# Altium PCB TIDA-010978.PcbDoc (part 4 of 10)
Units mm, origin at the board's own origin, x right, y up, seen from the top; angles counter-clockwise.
Board outline 243.95 x 94.85 mm, 4 copper layers (Top Layer, Mid Layer 1, Mid Layer 2, Bottom Layer), stack 1.623 mm thick; 865 components, 374 nets, 2308 pads, 2132 vias.
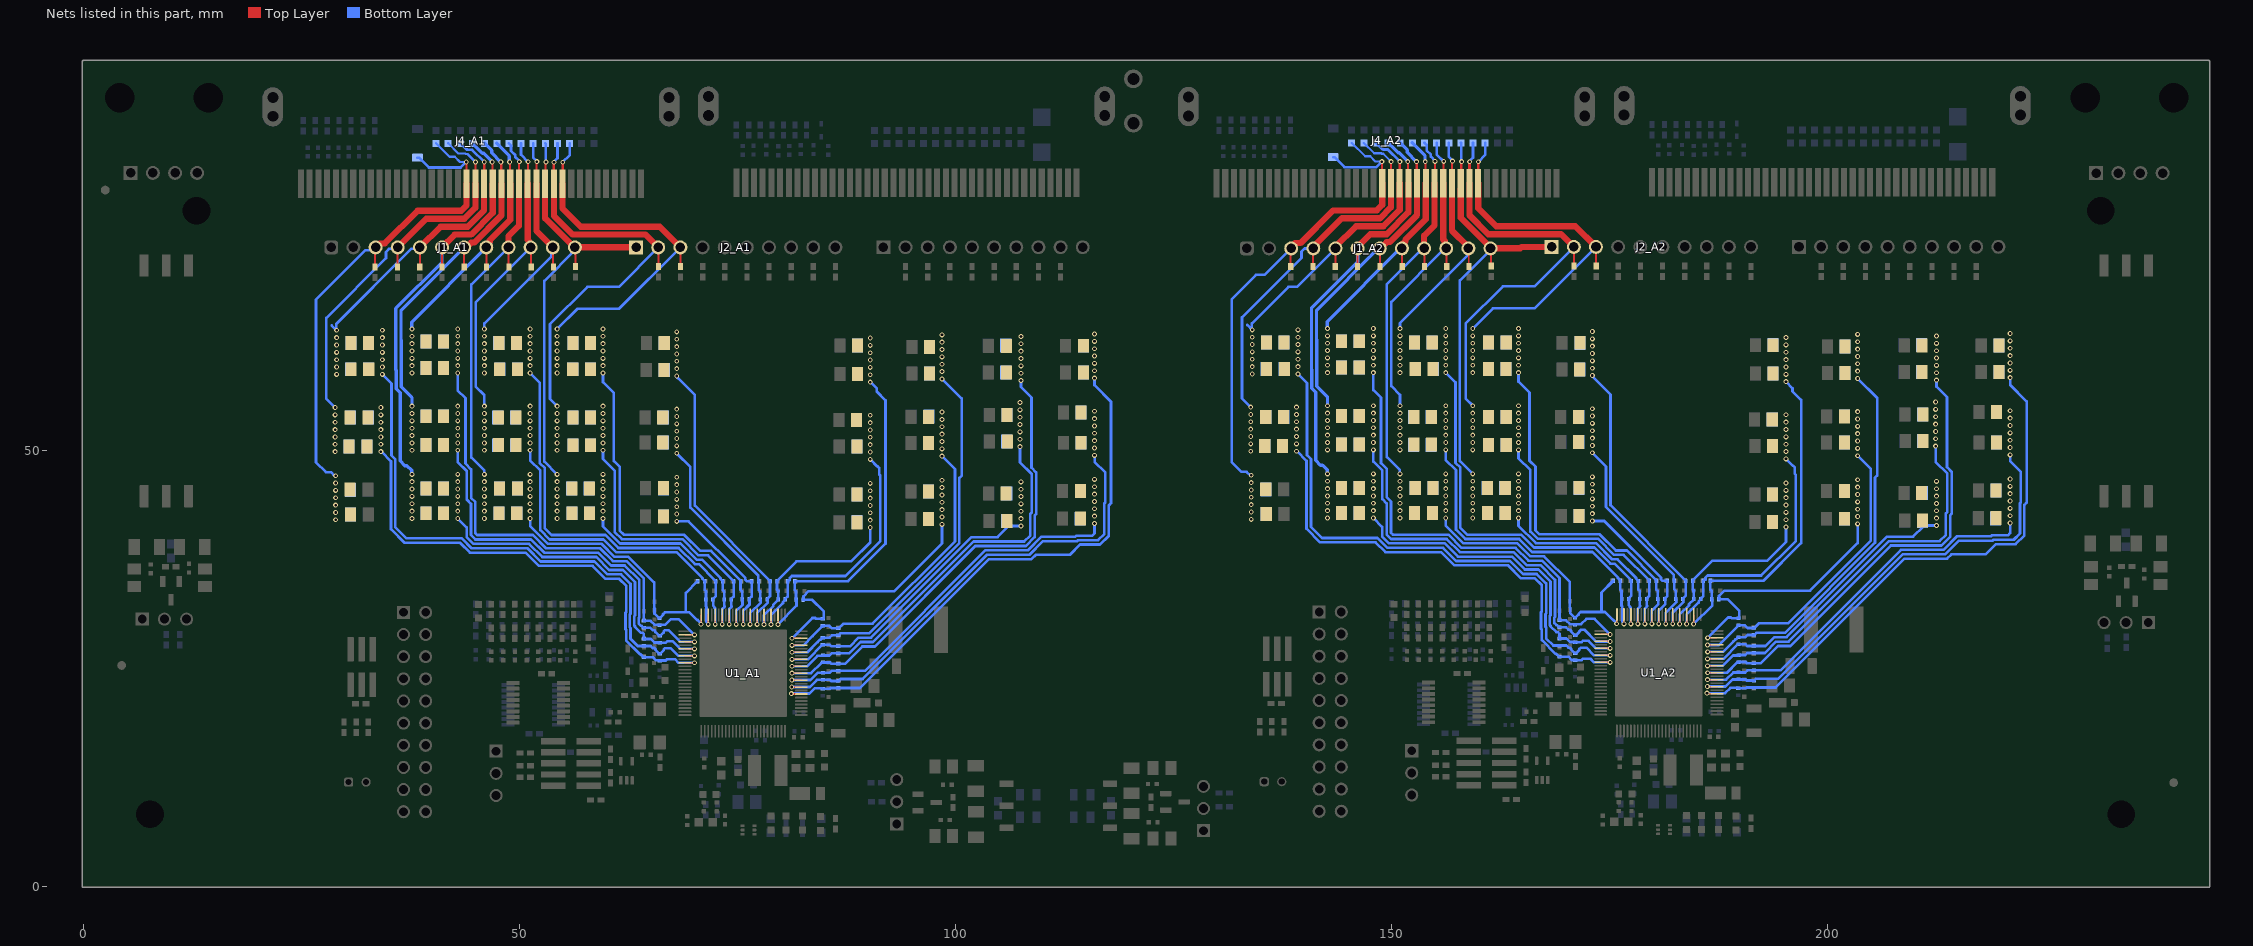
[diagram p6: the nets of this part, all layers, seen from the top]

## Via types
v1: diameter 0.559, hole 0.305, Top Layer to Bottom Layer, tented both sides, 1735 vias
v2: diameter 0.47, hole 0.2, Top Layer to Bottom Layer, tented both sides, 269 vias
v3: diameter 0.5, hole 0.2, Top Layer to Bottom Layer, tented both sides, 128 vias

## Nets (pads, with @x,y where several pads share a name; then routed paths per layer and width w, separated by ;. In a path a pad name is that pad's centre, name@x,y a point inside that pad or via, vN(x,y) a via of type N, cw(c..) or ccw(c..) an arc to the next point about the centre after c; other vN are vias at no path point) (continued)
CB1_A1: C46_A1.1 C53_A1.2 R100_A1.2 R107_A1.2 R112_A1.2 R117_A1.2 U1_A1.60 | length 55.6
  Top Layer w0.178: U1_A1.60@68.982,25.649 68.987,25.644 70.066,25.644 v1(70.071,25.639)
  Bottom Layer w0.305: v1(34.11,49.854) 34.158,49.854 35.265,48.748 35.265,40.965 36.825,39.405 43.183,39.405 44.317,38.271 50.7,38.271 52.214,36.757 58.392,36.757 59.874,35.274 61.443,35.274 62.235,34.482 62.235,31.473 62.155,31.393 62.155,29.506 62.235,29.426 62.235,28.18 63.797,26.618 63.897,26.618 64.222,26.293 65.285,26.293 65.66,25.918 66.037,25.918 C46_A1.1@66.085,25.871 66.114,25.9 66.792,25.9 66.944,26.053 67.815,26.053 68.229,25.639 v1(70.071,25.639)
  other v1: 34.11,50.697 34.11,51.54 34.11,52.383 34.11,53.226 34.11,54.069 34.11,54.912
CB1_A2: C46_A2.1 C53_A2.2 R100_A2.2 R107_A2.2 R112_A2.2 R117_A2.2 U1_A2.60 | length 55.6
  Top Layer w0.178: U1_A2.60@173.982,25.699 173.987,25.694 175.066,25.694 v1(175.071,25.689)
  Bottom Layer w0.305: v1(139.11,49.904) 139.158,49.904 140.265,48.798 140.265,41.015 141.825,39.455 148.183,39.455 149.317,38.321 155.7,38.321 157.214,36.807 163.392,36.807 164.874,35.324 166.443,35.324 167.235,34.532 167.235,31.523 167.155,31.443 167.155,29.556 167.235,29.476 167.235,28.23 168.797,26.668 168.897,26.668 169.222,26.343 170.285,26.343 170.66,25.968 171.037,25.968 C46_A2.1@171.085,25.921 171.114,25.95 171.792,25.95 171.944,26.103 172.815,26.103 173.229,25.689 v1(175.071,25.689)
  other v1: 139.11,50.747 139.11,51.59 139.11,52.433 139.11,53.276 139.11,54.119 139.11,54.962
CB2_A1: C42_A1.1 C46_A1.2 R80_A1.2 R85_A1.2 R90_A1.2 R95_A1.2 U1_A1.58 | length 64
  Top Layer w0.178: U1_A1.58@68.982,26.449 68.987,26.444 70.066,26.444 v1(70.071,26.439)
  Bottom Layer w0.305: v1(34.28,58.713) 35.318,57.674 35.318,49.408 35.769,48.957 35.769,41.174 37.034,39.909 43.392,39.909 44.526,38.776 50.909,38.776 52.423,37.262 58.601,37.262 60.083,35.779 61.652,35.779 62.74,34.691 62.74,31.264 62.66,31.184 62.66,29.715 62.74,29.635 62.74,28.397 63.565,27.572 C42_A1.1@64.272,27.572 65.044,27.572 65.282,27.333 65.464,27.333 65.593,27.205 65.593,27.112 66.035,26.671 C46_A1.2@66.085,26.671 ; C46_A1.2@66.135,26.671 66.533,27.069 66.533,27.148 66.711,27.327 67.341,27.327 68.229,26.439 v1(70.071,26.439)
  other v1: 34.28,59.556 34.28,60.398 34.28,61.241 34.28,62.084 34.28,62.927 34.28,63.77
CB2_A2: C42_A2.1 C46_A2.2 R80_A2.2 R85_A2.2 R90_A2.2 R95_A2.2 U1_A2.58 | length 64
  Top Layer w0.178: U1_A2.58@173.982,26.499 173.987,26.494 175.066,26.494 v1(175.071,26.489)
  Bottom Layer w0.305: v1(139.28,58.763) 140.318,57.724 140.318,49.458 140.769,49.007 140.769,41.224 142.034,39.959 148.392,39.959 149.526,38.826 155.909,38.826 157.423,37.312 163.601,37.312 165.083,35.829 166.652,35.829 167.74,34.741 167.74,31.314 167.66,31.234 167.66,29.765 167.74,29.685 167.74,28.447 168.565,27.622 C42_A2.1@169.272,27.622 170.044,27.622 170.282,27.383 170.464,27.383 170.593,27.255 170.593,27.162 171.035,26.721 C46_A2.2@171.085,26.721 ; C46_A2.2@171.135,26.721 171.533,27.119 171.533,27.198 171.711,27.377 172.341,27.377 173.229,26.489 v1(175.071,26.489)
  other v1: 139.28,59.606 139.28,60.448 139.28,61.291 139.28,62.134 139.28,62.977 139.28,63.82
CB3_A1: C34_A1.1 C42_A1.2 R58_A1.2 R62_A1.2 R66_A1.2 R72_A1.2 U1_A1.56 | length 38.6
  Top Layer w0.178: U1_A1.56@68.982,27.249 68.987,27.244 70.066,27.244 v1(70.071,27.239)
  Bottom Layer w0.305: v1(42.921,42.194) 43.937,41.179 43.937,40.414 43.937,40.079 44.735,39.281 51.118,39.281 52.633,37.766 58.81,37.766 60.292,36.284 61.861,36.284 63.245,34.9 63.245,31.055 63.165,30.975 63.165,29.924 63.245,29.844 63.245,29.758 63.906,29.097 64.094,29.097 64.272,28.919 C42_A1.2@64.272,28.372 65.069,28.372 65.469,27.972 65.987,27.972 66.035,27.924 C34_A1.1@66.085,27.924 66.114,27.954 66.792,27.954 66.944,28.106 67.589,28.106 68.456,27.239 v1(70.071,27.239)
  other v1: 42.921,43.037 42.921,43.88 42.921,44.723 42.921,45.566 42.921,46.409 42.921,47.25
CB3_A2: C34_A2.1 C42_A2.2 R58_A2.2 R62_A2.2 R66_A2.2 R72_A2.2 U1_A2.56 | length 38.6
  Top Layer w0.178: U1_A2.56@173.982,27.299 173.987,27.294 175.066,27.294 v1(175.071,27.289)
  Bottom Layer w0.305: v1(147.921,42.244) 148.937,41.229 148.937,40.464 148.937,40.129 149.735,39.331 156.118,39.331 157.633,37.816 163.81,37.816 165.292,36.334 166.861,36.334 168.245,34.95 168.245,31.105 168.165,31.025 168.165,29.974 168.245,29.894 168.245,29.808 168.906,29.147 169.094,29.147 169.272,28.969 C42_A2.2@169.272,28.422 170.069,28.422 170.469,28.022 170.987,28.022 171.035,27.974 C34_A2.1@171.085,27.974 171.114,28.004 171.792,28.004 171.944,28.156 172.589,28.156 173.456,27.289 v1(175.071,27.289)
  other v1: 147.921,43.087 147.921,43.93 147.921,44.773 147.921,45.616 147.921,46.459 147.921,47.3
CB4_A1: C25_A1.1 C34_A1.2 R38_A1.2 R42_A1.2 R46_A1.2 R51_A1.2 U1_A1.54 | length 45.8
  Top Layer w0.178: U1_A1.54@68.982,28.049 68.987,28.044 70.066,28.044 v1(70.071,28.039)
  Bottom Layer w0.305: v1(42.921,50.01) 42.921,48.655 43.957,47.619 43.957,44.35 44.442,43.865 44.442,40.919 44.442,40.288 44.944,39.786 51.327,39.786 52.842,38.271 59.019,38.271 60.502,36.789 62.07,36.789 63.75,35.109 63.75,30.846 63.67,30.766 63.67,30.133 63.906,29.897 63.975,29.897 64.175,29.697 64.225,29.697 C25_A1.1@64.272,29.65 65.008,29.65 65.276,29.381 65.459,29.381 65.588,29.252 65.588,29.171 66.035,28.724 66.135,28.724 66.533,29.122 66.533,29.202 66.711,29.38 67.114,29.38 68.456,28.039 v1(70.071,28.039)
  other v1: 42.921,50.853 42.921,51.696 42.921,52.539 42.921,53.382 42.921,54.225 42.921,55.068
CB4_A2: C25_A2.1 C34_A2.2 R38_A2.2 R42_A2.2 R46_A2.2 R51_A2.2 U1_A2.54 | length 45.8
  Top Layer w0.178: U1_A2.54@173.982,28.099 173.987,28.094 175.066,28.094 v1(175.071,28.089)
  Bottom Layer w0.305: v1(147.921,50.06) 147.921,48.705 148.957,47.669 148.957,44.4 149.442,43.915 149.442,40.969 149.442,40.338 149.944,39.836 156.327,39.836 157.842,38.321 164.019,38.321 165.502,36.839 167.07,36.839 168.75,35.159 168.75,30.896 168.67,30.816 168.67,30.183 168.906,29.947 168.975,29.947 169.175,29.747 169.225,29.747 C25_A2.1@169.272,29.7 170.008,29.7 170.276,29.431 170.459,29.431 170.588,29.302 170.588,29.221 171.035,28.774 171.135,28.774 171.533,29.172 171.533,29.252 171.711,29.43 172.114,29.43 173.456,28.089 v1(175.071,28.089)
  other v1: 147.921,50.903 147.921,51.746 147.921,52.589 147.921,53.432 147.921,54.275 147.921,55.118
CB5_A1: C12_A1.1 C25_A1.2 R21_A1.2 R25_A1.2 R29_A1.2 R33_A1.2 U1_A1.52 | length 53.6
  Top Layer w0.178: U1_A1.52@68.982,28.849 68.987,28.844 70.066,28.844 v1(70.071,28.839)
  Bottom Layer w0.305: v1(42.921,58.869) 42.921,56.873 43.804,55.989 43.804,48.486 44.462,47.829 44.462,44.559 44.947,44.074 44.947,41.337 44.947,40.497 45.153,40.29 51.536,40.29 53.051,38.776 59.228,38.776 60.711,37.293 62.279,37.293 64.272,35.3 C25_A1.2@64.272,30.45 65.036,30.45 65.472,30.013 65.956,30.013 66.004,29.965 C12_A1.1@66.054,29.965 66.102,30.013 66.736,30.013 67.345,30.622 68.281,30.622 70.064,28.839 v1(70.071,28.839)
  other v1: 42.921,59.712 42.921,60.555 42.921,61.398 42.921,62.24 42.921,63.083 42.921,63.926
CB5_A2: C12_A2.1 C25_A2.2 R21_A2.2 R25_A2.2 R29_A2.2 R33_A2.2 U1_A2.52 | length 53.6
  Top Layer w0.178: U1_A2.52@173.982,28.899 173.987,28.894 175.066,28.894 v1(175.071,28.889)
  Bottom Layer w0.305: v1(147.921,58.919) 147.921,56.923 148.804,56.039 148.804,48.536 149.462,47.879 149.462,44.609 149.947,44.124 149.947,41.387 149.947,40.547 150.153,40.34 156.536,40.34 158.051,38.826 164.228,38.826 165.711,37.343 167.279,37.343 169.272,35.35 C25_A2.2@169.272,30.5 170.036,30.5 170.472,30.063 170.956,30.063 171.004,30.015 C12_A2.1@171.054,30.015 171.102,30.063 171.736,30.063 172.345,30.672 173.281,30.672 175.064,28.889 v1(175.071,28.889)
  other v1: 147.921,59.762 147.921,60.605 147.921,61.448 147.921,62.29 147.921,63.133 147.921,63.976
CB6_A1: C12_A1.2 C54_A1.1 R2_A1.2 R8_A1.2 R12_A1.2 R16_A1.2 U1_A1.50 | length 33
  Top Layer w0.178: v1(70.821,30.064) 70.846,30.089 70.846,31.112 U1_A1.50@70.857,31.124
  Bottom Layer w0.305: v1(51.22,42.194) 51.22,41.32 53.26,39.281 59.437,39.281 60.92,37.798 62.488,37.798 65.447,34.84 65.447,31.955 65.488,31.913 65.488,31.281 66.004,30.765 66.104,30.765 66.465,31.127 66.465,31.206 66.681,31.422 69.083,31.422 ; 70.399,30.508 69.485,31.422 69.083,31.422 ; 70.433,30.542 70.433,30.52 70.821,30.133 v1(70.821,30.064) ; C54_A1.1@70.433,34.999 69.083,33.649 69.083,31.422
  other v1: 51.22,43.037 51.22,43.88 51.22,44.723 51.22,45.566 51.22,46.409 51.22,47.25
CB6_A2: C12_A2.2 C54_A2.1 R2_A2.2 R8_A2.2 R12_A2.2 R16_A2.2 U1_A2.50 | length 33
  Top Layer w0.178: v1(175.821,30.114) 175.846,30.139 175.846,31.162 U1_A2.50@175.857,31.174
  Bottom Layer w0.305: v1(156.22,42.244) 156.22,41.37 158.26,39.331 164.437,39.331 165.92,37.848 167.488,37.848 170.447,34.89 170.447,32.005 170.488,31.963 170.488,31.331 171.004,30.815 171.104,30.815 171.465,31.177 171.465,31.256 171.681,31.472 174.083,31.472 ; 175.399,30.558 174.485,31.472 174.083,31.472 ; 175.433,30.592 175.433,30.57 175.821,30.183 v1(175.821,30.114) ; C54_A2.1@175.433,35.049 174.083,33.699 174.083,31.472
  other v1: 156.22,43.087 156.22,43.93 156.22,44.773 156.22,45.616 156.22,46.459 156.22,47.3
CB7_A1: C47_A1.1 C54_A1.2 R101_A1.2 R108_A1.2 R113_A1.2 R118_A1.2 U1_A1.48 | length 37.2
  Top Layer w0.178: v1(71.657,30.05) U1_A1.48@71.657,31.124
  Bottom Layer w0.305: v1(51.22,50.01) 51.22,48.856 52.401,47.676 52.401,40.854 53.469,39.786 59.646,39.786 61.129,38.303 68.048,38.303 70.986,35.365 70.986,35.296 71.186,35.096 71.186,35.046 C54_A1.2@71.233,34.999 71.233,34.004 71.385,33.852 71.385,32.117 71.457,32.046 71.457,30.319 71.657,30.118 v1(71.657,30.05)
  other v1: 51.22,50.853 51.22,51.696 51.22,52.539 51.22,53.382 51.22,54.225 51.22,55.068
CB7_A2: C47_A2.1 C54_A2.2 R101_A2.2 R108_A2.2 R113_A2.2 R118_A2.2 U1_A2.48 | length 37.2
  Top Layer w0.178: v1(176.657,30.1) U1_A2.48@176.657,31.174
  Bottom Layer w0.305: v1(156.22,50.06) 156.22,48.906 157.401,47.726 157.401,40.904 158.469,39.836 164.646,39.836 166.129,38.353 173.048,38.353 175.986,35.415 175.986,35.346 176.186,35.146 176.186,35.096 C54_A2.2@176.233,35.049 176.233,34.054 176.385,33.902 176.385,32.167 176.457,32.096 176.457,30.369 176.657,30.168 v1(176.657,30.1)
  other v1: 156.22,50.903 156.22,51.746 156.22,52.589 156.22,53.432 156.22,54.275 156.22,55.118
CB8_A1: C43_A1.1 C47_A1.2 R81_A1.2 R86_A1.2 R91_A1.2 R96_A1.2 U1_A1.46 | length 46.9
  Top Layer w0.178: v1(72.457,30.05) U1_A1.46@72.457,31.124
  Bottom Layer w0.305: v1(51.22,58.869) 52.343,57.746 52.343,48.521 52.905,47.959 52.905,41.063 53.678,40.29 59.855,40.29 61.338,38.808 68.257,38.808 70.109,36.956 70.562,36.956 72.446,35.072 72.446,35.022 C43_A1.1@72.494,34.974 72.494,33.264 72.233,33.003 72.233,32.953 C47_A1.2@72.185,32.905 72.204,32.886 72.204,32.198 72.357,32.046 72.357,31.976 72.457,31.876 v1(72.457,30.05)
  other v1: 51.22,59.712 51.22,60.555 51.22,61.398 51.22,62.24 51.22,63.083 51.22,63.926
CB8_A2: C43_A2.1 C47_A2.2 R81_A2.2 R86_A2.2 R91_A2.2 R96_A2.2 U1_A2.46 | length 46.9
  Top Layer w0.178: v1(177.457,30.1) U1_A2.46@177.457,31.174
  Bottom Layer w0.305: v1(156.22,58.919) 157.343,57.796 157.343,48.571 157.905,48.009 157.905,41.113 158.678,40.34 164.855,40.34 166.338,38.858 173.257,38.858 175.109,37.006 175.562,37.006 177.446,35.122 177.446,35.072 C43_A2.1@177.494,35.024 177.494,33.314 177.233,33.053 177.233,33.003 C47_A2.2@177.185,32.955 177.204,32.936 177.204,32.248 177.357,32.096 177.357,32.026 177.457,31.926 v1(177.457,30.1)
  other v1: 156.22,59.762 156.22,60.605 156.22,61.448 156.22,62.29 156.22,63.133 156.22,63.976
CB9_A1: C35_A1.1 C43_A1.2 R59_A1.2 R63_A1.2 R67_A1.2 R73_A1.2 U1_A1.44 | length 23.5
  Top Layer w0.178: v1(73.257,30.05) U1_A1.44@73.257,31.092
  Bottom Layer w0.305: v1(59.576,42.194) 59.576,41.284 61.547,39.313 68.466,39.313 70.318,37.461 70.927,37.461 73.046,35.341 73.046,35.272 73.294,35.024 73.294,34.004 73.476,33.823 73.476,32.167 73.547,32.096 73.257,31.805 v1(73.257,30.05)
  other v1: 59.576,43.037 59.576,43.88 59.576,44.723 59.576,45.566 59.576,46.409 59.576,47.25
CB9_A2: C35_A2.1 C43_A2.2 R59_A2.2 R63_A2.2 R67_A2.2 R73_A2.2 U1_A2.44 | length 23.5
  Top Layer w0.178: v1(178.257,30.1) U1_A2.44@178.257,31.142
  Bottom Layer w0.305: v1(164.576,42.244) 164.576,41.334 166.547,39.363 173.466,39.363 175.318,37.511 175.927,37.511 178.046,35.391 178.046,35.322 178.294,35.074 178.294,34.054 178.476,33.873 178.476,32.217 178.547,32.146 178.257,31.855 v1(178.257,30.1)
  other v1: 164.576,43.087 164.576,43.93 164.576,44.773 164.576,45.616 164.576,46.459 164.576,47.3
CB10_A1: C26_A1.1 C35_A1.2 R39_A1.2 R43_A1.2 R47_A1.2 R52_A1.2 U1_A1.42 | length 32.2
  Top Layer w0.178: v1@74.065,30.028 U1_A1.42@74.065,31.1
  Bottom Layer w0.305: v1(59.576,50.01) 59.576,49.025 60.926,47.676 60.926,40.648 61.756,39.817 68.675,39.817 70.527,37.966 71.619,37.966 74.509,35.076 74.509,35.026 C26_A1.1@74.556,34.979 74.556,33.231 74.276,32.95 74.276,32.167 74.347,32.096 74.057,31.805 v1(74.057,30.05)
  other v1: 59.576,50.853 59.576,51.696 59.576,52.539 59.576,53.382 59.576,54.225 59.576,55.068
CB10_A2: C26_A2.1 C35_A2.2 R39_A2.2 R43_A2.2 R47_A2.2 R52_A2.2 U1_A2.42 | length 32.2
  Top Layer w0.178: v1@179.065,30.078 U1_A2.42@179.065,31.15
  Bottom Layer w0.305: v1(164.576,50.06) 164.576,49.075 165.926,47.726 165.926,40.698 166.756,39.867 173.675,39.867 175.527,38.016 176.619,38.016 179.509,35.126 179.509,35.076 C26_A2.1@179.556,35.029 179.556,33.281 179.276,33 179.276,32.217 179.347,32.146 179.057,31.855 v1(179.057,30.1)
  other v1: 164.576,50.903 164.576,51.746 164.576,52.589 164.576,53.432 164.576,54.275 164.576,55.118
CB11_A1: C13_A1.1 C26_A1.2 R22_A1.2 R26_A1.2 R30_A1.2 R34_A1.2 U1_A1.40 | length 41.6
  Top Layer w0.178: v1@74.865,30.028 U1_A1.40@74.865,31.1
  Bottom Layer w0.305: v1(59.576,58.869) 59.576,57.825 60.829,56.572 60.829,48.76 61.516,48.073 61.516,40.771 61.965,40.322 68.884,40.322 70.736,38.471 71.983,38.471 75.356,35.098 75.356,34.01 75.538,33.828 C13_A1.1@75.538,32.907 75.586,32.86 75.586,32.354 75.61,32.33 74.857,31.578 v1(74.857,30.05)
  other v1: 59.576,59.712 59.576,60.555 59.576,61.398 59.576,62.24 59.576,63.083 59.576,63.926
CB11_A2: C13_A2.1 C26_A2.2 R22_A2.2 R26_A2.2 R30_A2.2 R34_A2.2 U1_A2.40 | length 41.6
  Top Layer w0.178: v1@179.865,30.078 U1_A2.40@179.865,31.15
  Bottom Layer w0.305: v1(164.576,58.919) 164.576,57.875 165.829,56.622 165.829,48.81 166.516,48.123 166.516,40.821 166.965,40.372 173.884,40.372 175.736,38.521 176.983,38.521 180.356,35.148 180.356,34.06 180.538,33.878 C13_A2.1@180.538,32.957 180.586,32.91 180.586,32.404 180.61,32.38 179.857,31.628 v1(179.857,30.1)
  other v1: 164.576,59.762 164.576,60.605 164.576,61.448 164.576,62.29 164.576,63.133 164.576,63.976
CB12_A1: C13_A1.2 C55_A1.1 R3_A1.2 R9_A1.2 R13_A1.2 R17_A1.2 U1_A1.38 | length 18
  Top Layer w0.178: v1(75.657,30.05) U1_A1.38@75.657,31.092
  Bottom Layer w0.305: v1(68.032,41.854) 69.4,41.854 75.909,35.345 75.909,35.163 76.087,34.984 C55_A1.1@76.631,34.984 76.631,33.25 76.338,32.957 C13_A1.2@76.338,32.907 76.386,32.86 76.386,32.378 76.41,32.354 75.657,31.602 v1(75.657,30.05)
  other v1: 68.032,42.697 68.032,43.54 68.032,44.383 68.032,45.225 68.032,46.068 68.032,46.911
CB12_A2: C13_A2.2 C55_A2.1 R3_A2.2 R9_A2.2 R13_A2.2 R17_A2.2 U1_A2.38 | length 18
  Top Layer w0.178: v1(180.657,30.1) U1_A2.38@180.657,31.142
  Bottom Layer w0.305: v1(173.032,41.904) 174.4,41.904 180.909,35.395 180.909,35.213 181.087,35.034 C55_A2.1@181.631,35.034 181.631,33.3 181.338,33.007 C13_A2.2@181.338,32.957 181.386,32.91 181.386,32.428 181.41,32.404 180.657,31.652 v1(180.657,30.1)
  other v1: 173.032,42.747 173.032,43.59 173.032,44.433 173.032,45.275 173.032,46.118 173.032,46.961
CB13_A1: C48_A1.1 C55_A1.2 R102_A1.2 R109_A1.2 R114_A1.2 R119_A1.2 U1_A1.36 | length 25.2
  Top Layer w0.178: v1@76.465,30.028 U1_A1.36@76.465,31.1
  Bottom Layer w0.305: v1(68.032,49.67) 69.604,48.098 69.604,43.451 77.383,35.672 77.383,35.032 C55_A1.2@77.431,34.984 77.431,34.014 77.615,33.83 C48_A1.1@77.615,32.908 77.663,32.86 77.663,32.593 77.687,32.569 76.457,31.339 v1(76.457,30.05)
  other v1: 68.032,50.513 68.032,51.356 68.032,52.199 68.032,53.041 68.032,53.884 68.032,54.727
CB13_A2: C48_A2.1 C55_A2.2 R102_A2.2 R109_A2.2 R114_A2.2 R119_A2.2 U1_A2.36 | length 25.2
  Top Layer w0.178: v1@181.465,30.078 U1_A2.36@181.465,31.15
  Bottom Layer w0.305: v1(173.032,49.72) 174.604,48.148 174.604,43.501 182.383,35.722 182.383,35.082 C55_A2.2@182.431,35.034 182.431,34.064 182.615,33.88 C48_A2.1@182.615,32.958 182.663,32.91 182.663,32.643 182.687,32.619 181.457,31.389 v1(181.457,30.1)
  other v1: 173.032,50.563 173.032,51.406 173.032,52.249 173.032,53.091 173.032,53.934 173.032,54.777
CB14_A1: C44_A1.1 C48_A1.2 R82_A1.2 R87_A1.2 R92_A1.2 R97_A1.2 U1_A1.34 | length 34.7
  Top Layer w0.178: v1@77.265,30.028 U1_A1.34@77.265,31.1
  Bottom Layer w0.305: v1(68.032,58.528) 68.032,58.459 68.159,58.332 68.159,58.304 70.109,56.355 70.109,43.66 78.734,35.036 78.734,33.276 78.415,32.958 C48_A1.2@78.415,32.908 78.463,32.86 78.463,32.593 78.487,32.569 77.257,31.339 v1(77.257,30.05)
  other v1: 68.032,59.371 68.032,60.214 68.032,61.057 68.032,61.9 68.032,62.743 68.032,63.586
CB14_A2: C44_A2.1 C48_A2.2 R82_A2.2 R87_A2.2 R92_A2.2 R97_A2.2 U1_A2.34 | length 34.7
  Top Layer w0.178: v1@182.265,30.078 U1_A2.34@182.265,31.15
  Bottom Layer w0.305: v1(173.032,58.578) 173.032,58.509 173.159,58.382 173.159,58.354 175.109,56.405 175.109,43.71 183.734,35.086 183.734,33.326 183.415,33.008 C48_A2.2@183.415,32.958 183.463,32.91 183.463,32.643 183.487,32.619 182.257,31.389 v1(182.257,30.1)
  other v1: 173.032,59.421 173.032,60.264 173.032,61.107 173.032,61.95 173.032,62.793 173.032,63.636
CB15_A1: C36_A1.1 C44_A1.2 R60_A1.2 R64_A1.2 R68_A1.2 R74_A1.2 U1_A1.32 | length 21.2
  Top Layer w0.178: v1(78.046,30.039) 78.052,30.044 78.052,31.087 U1_A1.32@78.057,31.092
  Bottom Layer w0.305: v1(78.046,30.039) 78.046,31.102 79.118,32.174 79.118,32.308 79.668,32.858 79.668,33.856 79.534,33.99 79.534,35.036 81.771,37.273 88.045,37.273 90.235,39.462 v1(90.235,41.154) ; 79.639,33.736 79.639,33.786 79.739,33.886
  other v1: 90.235,41.997 90.235,42.84 90.235,43.683 90.235,44.526 90.235,45.369 90.235,46.212
CB15_A2: C36_A2.1 C44_A2.2 R60_A2.2 R64_A2.2 R68_A2.2 R74_A2.2 U1_A2.32 | length 21.2
  Top Layer w0.178: v1(183.046,30.089) 183.052,30.094 183.052,31.137 U1_A2.32@183.057,31.142
  Bottom Layer w0.305: v1(183.046,30.089) 183.046,31.152 184.118,32.224 184.118,32.358 184.668,32.908 184.668,33.906 184.534,34.04 184.534,35.086 186.771,37.323 193.045,37.323 195.235,39.512 v1(195.235,41.204) ; 184.639,33.786 184.639,33.836 184.739,33.936
  other v1: 195.235,42.047 195.235,42.89 195.235,43.733 195.235,44.576 195.235,45.419 195.235,46.262
CB16_A1: C27_A1.1 C36_A1.2 R40_A1.2 R44_A1.2 R48_A1.2 R53_A1.2 U1_A1.30 | length 29.4
  Top Layer w0.178: v1@78.865,30.028 U1_A1.30@78.865,31.1
  Bottom Layer w0.305: v1(78.846,30.039) 78.857,30.05 78.857,31.124 80.22,32.487 80.22,32.61 80.468,32.858 80.468,32.958 80.761,33.25 C27_A1.1@80.761,34.999 80.858,35.096 81.008,35.096 81.008,35.365 81.244,35.601 87.393,35.601 91.367,39.575 91.367,47.148 91.255,47.26 91.255,47.997 91.076,48.175 91.03,48.175 v1(90.235,48.97)
  other v1: 90.235,49.813 90.235,50.656 90.235,51.499 90.235,52.342 90.235,53.185 90.235,54.028
CB16_A2: C27_A2.1 C36_A2.2 R40_A2.2 R44_A2.2 R48_A2.2 R53_A2.2 U1_A2.30 | length 29.4
  Top Layer w0.178: v1@183.865,30.078 U1_A2.30@183.865,31.15
  Bottom Layer w0.305: v1(183.846,30.089) 183.857,30.1 183.857,31.174 185.22,32.537 185.22,32.66 185.468,32.908 185.468,33.008 185.761,33.3 C27_A2.1@185.761,35.049 185.858,35.146 186.008,35.146 186.008,35.415 186.244,35.651 192.393,35.651 196.367,39.625 196.367,47.198 196.255,47.31 196.255,48.047 196.076,48.225 196.03,48.225 v1(195.235,49.02)
  other v1: 195.235,49.863 195.235,50.706 195.235,51.549 195.235,52.392 195.235,53.235 195.235,54.078
CB17_A1: C14_A1.1 C27_A1.2 R23_A1.2 R27_A1.2 R31_A1.2 R35_A1.2 U1_A1.28 | length 38.5
  Top Layer w0.178: v1@79.665,30.028 U1_A1.28@79.665,31.1
  Bottom Layer w0.305: v1(79.646,30.039) 79.646,30.04 81.79,32.184 81.766,32.208 81.766,32.837 C14_A1.1@81.719,32.884 81.719,33.839 81.561,33.997 C27_A1.2@81.561,34.999 87.678,34.999 91.979,39.3 91.979,55.736 90.992,56.724 90.992,57.071 v1(90.235,57.829)
  other v1: 90.235,58.671 90.235,59.514 90.235,60.357 90.235,61.2 90.235,62.043 90.235,62.886
CB17_A2: C14_A2.1 C27_A2.2 R23_A2.2 R27_A2.2 R31_A2.2 R35_A2.2 U1_A2.28 | length 38.5
  Top Layer w0.178: v1@184.665,30.078 U1_A2.28@184.665,31.15
  Bottom Layer w0.305: v1(184.646,30.089) 184.646,30.09 186.79,32.234 186.766,32.258 186.766,32.887 C14_A2.1@186.719,32.934 186.719,33.889 186.561,34.047 C27_A2.2@186.561,35.049 192.678,35.049 196.979,39.35 196.979,55.786 195.992,56.774 195.992,57.121 v1(195.235,57.879)
  other v1: 195.235,58.721 195.235,59.564 195.235,60.407 195.235,61.25 195.235,62.093 195.235,62.936
CB18_A1: C14_A1.2 C56_A1.1 R4_A1.2 R10_A1.2 R14_A1.2 R18_A1.2 U1_A1.23 | length 30.4
  Top Layer w0.178: v1(81.258,28.449) U1_A1.23@82.301,28.449
  Bottom Layer w0.305: v1(81.258,28.449) 81.26,28.449 83.589,30.778 83.933,30.778 84.024,30.687 84.843,30.687 84.89,30.734 84.89,31.029 84.9,31.039 84.9,31.503 83.519,32.884 C14_A1.2@82.519,32.884 82.566,32.932 82.566,33.263 83.166,33.863 92.993,33.863 98.46,39.331 v1(98.46,41.519)
  other v1: 98.46,42.362 98.46,43.204 98.46,44.047 98.46,44.89 98.46,45.733 98.46,46.576
CB18_A2: C14_A2.2 C56_A2.1 R4_A2.2 R10_A2.2 R14_A2.2 R18_A2.2 U1_A2.23 | length 30.4
  Top Layer w0.178: v1(186.258,28.499) U1_A2.23@187.301,28.499
  Bottom Layer w0.305: v1(186.258,28.499) 186.26,28.499 188.589,30.828 188.933,30.828 189.024,30.737 189.843,30.737 189.89,30.784 189.89,31.079 189.9,31.089 189.9,31.553 188.519,32.934 C14_A2.2@187.519,32.934 187.566,32.982 187.566,33.313 188.166,33.913 197.993,33.913 203.46,39.381 v1(203.46,41.569)
  other v1: 203.46,42.412 203.46,43.254 203.46,44.097 203.46,44.94 203.46,45.783 203.46,46.626
CB19_A1: C49_A1.1 C56_A1.2 R103_A1.2 R110_A1.2 R115_A1.2 R120_A1.2 U1_A1.21 | length 35.4
  Top Layer w0.178: v1@81.236,27.64 U1_A1.21@82.309,27.64
  Bottom Layer w0.305: v1(81.246,27.639) 82.557,27.639 83.626,28.708 84.695,29.777 84.695,29.839 84.731,29.875 C56_A1.2@84.793,29.875 ; C56_A1.2@84.743,29.887 85.524,29.887 85.828,29.583 C49_A1.1@86.559,29.583 ; C49_A1.1@86.609,29.583 87.004,29.978 87.156,30.13 90.504,30.13 99.946,39.572 99.946,47.849 v1(98.46,49.335)
  other v1: 98.46,50.178 98.46,51.02 98.46,51.863 98.46,52.706 98.46,53.549 98.46,54.392
CB19_A2: C49_A2.1 C56_A2.2 R103_A2.2 R110_A2.2 R115_A2.2 R120_A2.2 U1_A2.21 | length 35.4
  Top Layer w0.178: v1@186.236,27.69 U1_A2.21@187.309,27.69
  Bottom Layer w0.305: v1(186.246,27.689) 187.557,27.689 188.626,28.758 189.695,29.827 189.695,29.889 189.731,29.925 C56_A2.2@189.793,29.925 ; C56_A2.2@189.743,29.937 190.524,29.937 190.828,29.633 C49_A2.1@191.559,29.633 ; C49_A2.1@191.609,29.633 192.004,30.028 192.156,30.18 195.504,30.18 204.946,39.622 204.946,47.899 v1(203.46,49.385)
  other v1: 203.46,50.228 203.46,51.07 203.46,51.913 203.46,52.756 203.46,53.599 203.46,54.442
CB20_A1: C45_A1.1 C49_A1.2 R83_A1.2 R88_A1.2 R93_A1.2 R98_A1.2 U1_A1.19 | length 45.3
  Top Layer w0.178: v1@81.236,26.84 U1_A1.19@82.309,26.84
  Bottom Layer w0.305: v1(81.258,26.849) 83.018,26.849 84.197,28.028 84.197,28.042 84.433,28.278 84.502,28.278 C45_A1.1@84.75,28.526 ; C45_A1.1@84.8,28.526 C45_A1.1@84.75,28.526 ; C49_A1.2@86.559,28.783 85.832,28.783 85.574,28.526 C45_A1.1@84.75,28.526 ; C49_A1.2@86.609,28.783 86.657,28.831 86.657,28.852 86.835,29.031 90.118,29.031 100.45,39.363 100.45,46.829 100.708,47.086 100.708,55.946 v1(98.46,58.193)
  other v1: 98.46,59.036 98.46,59.879 98.46,60.722 98.46,61.565 98.46,62.407 98.46,63.25
CB20_A2: C45_A2.1 C49_A2.2 R83_A2.2 R88_A2.2 R93_A2.2 R98_A2.2 U1_A2.19 | length 45.3
  Top Layer w0.178: v1@186.236,26.89 U1_A2.19@187.309,26.89
  Bottom Layer w0.305: v1(186.258,26.899) 188.018,26.899 189.197,28.078 189.197,28.092 189.433,28.328 189.502,28.328 C45_A2.1@189.75,28.576 ; C45_A2.1@189.8,28.576 C45_A2.1@189.75,28.576 ; C49_A2.2@191.559,28.833 190.832,28.833 190.574,28.576 C45_A2.1@189.75,28.576 ; C49_A2.2@191.609,28.833 191.657,28.881 191.657,28.902 191.835,29.081 195.118,29.081 205.45,39.413 205.45,46.879 205.708,47.136 205.708,55.996 v1(203.46,58.243)
  other v1: 203.46,59.086 203.46,59.929 203.46,60.772 203.46,61.615 203.46,62.457 203.46,63.3
CB21_A1: C37_A1.1 C45_A1.2 R61_A1.2 R65_A1.2 R69_A1.2 R75_A1.2 U1_A1.17 | length 33.8
  Top Layer w0.178: v1(81.246,26.039) 81.251,26.044 82.296,26.044 U1_A1.17@82.301,26.049
  Bottom Layer w0.305: v1(81.246,26.039) 83.063,26.039 84.75,27.726 85.576,27.726 85.783,27.518 87.892,27.518 88.9,28.526 90.327,28.526 101.852,40.05 104.815,40.05 105.988,41.223 106.361,41.223 106.47,41.333 v1(107.507,41.333)
  other v1: 107.507,42.176 107.507,43.019 107.507,43.861 107.507,44.704 107.507,45.547 107.507,46.39
CB21_A2: C37_A2.1 C45_A2.2 R61_A2.2 R65_A2.2 R69_A2.2 R75_A2.2 U1_A2.17 | length 33.8
  Top Layer w0.178: v1(186.246,26.089) 186.251,26.094 187.296,26.094 U1_A2.17@187.301,26.099
  Bottom Layer w0.305: v1(186.246,26.089) 188.063,26.089 189.75,27.776 190.576,27.776 190.783,27.568 192.892,27.568 193.9,28.576 195.327,28.576 206.852,40.1 209.815,40.1 210.988,41.273 211.361,41.273 211.47,41.383 v1(212.507,41.383)
  other v1: 212.507,42.226 212.507,43.069 212.507,43.911 212.507,44.754 212.507,45.597 212.507,46.44
CB22_A1: C28_A1.1 C37_A1.2 R41_A1.2 R45_A1.2 R49_A1.2 R54_A1.2 U1_A1.15 | length 45.4
  Top Layer w0.178: v1@81.236,25.24 U1_A1.15@82.309,25.24
  Bottom Layer w0.305: v1(81.246,25.239) 82.977,25.239 84.168,26.43 84.757,26.43 C28_A1.1@84.805,26.477 85.56,26.477 85.804,26.721 87.808,26.721 89.109,28.021 90.537,28.021 102.061,39.546 107.871,39.546 108.582,40.257 108.582,41.215 108.582,42.731 108.747,42.896 108.747,47.271 107.403,48.614 v1(107.403,50.433)
  other v1: 107.403,51.276 107.403,52.119 107.403,52.962 107.403,53.805 107.403,54.648 107.403,55.491
CB22_A2: C28_A2.1 C37_A2.2 R41_A2.2 R45_A2.2 R49_A2.2 R54_A2.2 U1_A2.15 | length 45.4
  Top Layer w0.178: v1@186.236,25.29 U1_A2.15@187.309,25.29
  Bottom Layer w0.305: v1(186.246,25.289) 187.977,25.289 189.168,26.48 189.757,26.48 C28_A2.1@189.805,26.527 190.56,26.527 190.804,26.771 192.808,26.771 194.109,28.071 195.537,28.071 207.061,39.596 212.871,39.596 213.582,40.307 213.582,41.265 213.582,42.781 213.747,42.946 213.747,47.321 212.403,48.664 v1(212.403,50.483)
  other v1: 212.403,51.326 212.403,52.169 212.403,53.012 212.403,53.855 212.403,54.698 212.403,55.541
CB23_A1: C15_A1.1 C28_A1.2 R24_A1.2 R28_A1.2 R32_A1.2 R36_A1.2 U1_A1.13 | length 54.3
  Top Layer w0.178: v1@81.236,24.44 U1_A1.13@82.309,24.44
  Bottom Layer w0.305: v1(81.258,24.449) 83.45,24.449 84.632,25.63 84.757,25.63 C28_A1.2@84.805,25.677 ; C28_A1.2@84.755,25.677 85.629,25.677 85.783,25.523 87.325,25.523 89.318,27.517 90.746,27.517 102.27,39.041 108.08,39.041 109.087,40.048 109.087,42.521 109.252,42.687 109.252,47.48 108.712,48.02 108.712,56.061 107.507,57.265 v1(107.507,58.007)
  other v1: 107.507,58.85 107.507,59.693 107.507,60.536 107.507,61.379 107.507,62.222 107.507,63.065
CB23_A2: C15_A2.1 C28_A2.2 R24_A2.2 R28_A2.2 R32_A2.2 R36_A2.2 U1_A2.13 | length 54.3
  Top Layer w0.178: v1@186.236,24.49 U1_A2.13@187.309,24.49
  Bottom Layer w0.305: v1(186.258,24.499) 188.45,24.499 189.632,25.68 189.757,25.68 C28_A2.2@189.805,25.727 ; C28_A2.2@189.755,25.727 190.629,25.727 190.783,25.573 192.325,25.573 194.318,27.567 195.746,27.567 207.27,39.091 213.08,39.091 214.087,40.098 214.087,42.571 214.252,42.737 214.252,47.53 213.712,48.07 213.712,56.111 212.507,57.315 v1(212.507,58.057)
  other v1: 212.507,58.9 212.507,59.743 212.507,60.586 212.507,61.429 212.507,62.272 212.507,63.115
CB24_A1: C15_A1.2 C57_A1.1 R5_A1.2 R11_A1.2 R15_A1.2 R19_A1.2 U1_A1.11 | length 43.9
  Top Layer w0.178: v1(81.24,23.662) 81.247,23.655 82.325,23.655 U1_A1.11@82.332,23.649
  Bottom Layer w0.305: v1(81.24,23.662) 83.377,23.662 84.198,24.482 85.56,24.482 85.804,24.726 89.6,24.726 103.41,38.536 108.289,38.536 109.854,40.101 113.738,40.101 113.843,40.206 115.678,40.206 115.943,40.471 v1(115.943,41.613)
  other v1: 115.943,42.456 115.943,43.299 115.943,44.142 115.943,44.985 115.943,45.828 115.943,46.671
CB24_A2: C15_A2.2 C57_A2.1 R5_A2.2 R11_A2.2 R15_A2.2 R19_A2.2 U1_A2.11 | length 43.9
  Top Layer w0.178: v1(186.24,23.712) 186.247,23.705 187.326,23.705 U1_A2.11@187.332,23.699
  Bottom Layer w0.305: v1(186.24,23.712) 188.377,23.712 189.198,24.532 190.56,24.532 190.804,24.776 194.6,24.776 208.41,38.586 213.289,38.586 214.854,40.151 218.738,40.151 218.843,40.256 220.678,40.256 220.943,40.521 v1(220.943,41.663)
  other v1: 220.943,42.506 220.943,43.349 220.943,44.192 220.943,45.035 220.943,45.878 220.943,46.721
CB25_A1: C50_A1.1 C57_A1.2 R104_A1.2 R111_A1.2 R116_A1.2 R121_A1.2 U1_A1.9 | length 53.9
  Top Layer w0.178: v1(81.221,22.863) 81.229,22.856 82.325,22.856 U1_A1.9@82.332,22.849
  Bottom Layer w0.305: v1(81.221,22.863) 83.293,22.863 84.112,23.682 85.618,23.682 85.747,23.553 86.609,23.553 86.829,23.773 89.361,23.773 103.619,38.031 108.498,38.031 110.063,39.596 113.947,39.596 114.052,39.701 116.361,39.701 117.073,40.412 117.073,43.907 117.167,44.002 117.167,47.497 115.971,48.693 115.971,49.401 v1(115.943,49.429)
  other v1: 115.943,50.272 115.943,51.115 115.943,51.958 115.943,52.801 115.943,53.644 115.943,54.487
CB25_A2: C50_A2.1 C57_A2.2 R104_A2.2 R111_A2.2 R116_A2.2 R121_A2.2 U1_A2.9 | length 53.9
  Top Layer w0.178: v1(186.221,22.913) 186.229,22.906 187.325,22.906 U1_A2.9@187.332,22.899
  Bottom Layer w0.305: v1(186.221,22.913) 188.293,22.913 189.112,23.732 190.618,23.732 190.747,23.603 191.609,23.603 191.829,23.823 194.361,23.823 208.619,38.081 213.498,38.081 215.063,39.646 218.947,39.646 219.052,39.751 221.361,39.751 222.073,40.462 222.073,43.957 222.167,44.052 222.167,47.547 220.971,48.743 220.971,49.451 v1(220.943,49.479)
  other v1: 220.943,50.322 220.943,51.165 220.943,52.008 220.943,52.851 220.943,53.694 220.943,54.537
CB26_A1: C41_A1.1 C50_A1.2 R84_A1.2 R89_A1.2 R94_A1.2 R99_A1.2 U1_A1.7 | length 64.1
  Top Layer w0.178: v1(81.18,22.104) 81.225,22.06 82.321,22.06 U1_A1.7@82.332,22.049
  Bottom Layer w0.305: v1(81.18,22.104) 81.189,22.114 83.257,22.114 83.854,22.71 84.727,22.71 C41_A1.1@84.775,22.663 85.621,22.663 85.712,22.754 89.055,22.754 103.828,37.526 108.707,37.526 109.212,38.031 113.143,38.031 114.308,39.196 116.57,39.196 117.577,40.203 117.577,43.685 117.842,43.95 117.842,55.577 115.943,57.476 v1(115.943,58.288)
  other v1: 115.943,59.131 115.943,59.973 115.943,60.816 115.943,61.659 115.943,62.502 115.943,63.345
CB26_A2: C41_A2.1 C50_A2.2 R84_A2.2 R89_A2.2 R94_A2.2 R99_A2.2 U1_A2.7 | length 64.1
  Top Layer w0.178: v1(186.18,22.154) 186.225,22.11 187.321,22.11 U1_A2.7@187.332,22.099
  Bottom Layer w0.305: v1(186.18,22.154) 186.189,22.164 188.257,22.164 188.854,22.76 189.727,22.76 C41_A2.1@189.775,22.713 190.621,22.713 190.712,22.804 194.055,22.804 208.828,37.576 213.707,37.576 214.212,38.081 218.143,38.081 219.308,39.246 221.57,39.246 222.577,40.253 222.577,43.735 222.842,44 222.842,55.627 220.943,57.526 v1(220.943,58.338)
  other v1: 220.943,59.181 220.943,60.023 220.943,60.866 220.943,61.709 220.943,62.552 220.943,63.395
CELL0_A1: C146_A1.2 D7_A1.1 J1_A1.3 J4_A1.10 R122_A1.1 R123_A1.1 R124_A1.1 R125_A1.1 R231_A1.1 | length 61.2
  Top Layer w0.229: R231_A1.1@33.445,71.032 33.445,73.229 J1_A1.3@33.499,73.282
  Top Layer w0.254: v1(43.892,83.062) 43.917,83.037 43.917,80.612 J4_A1.10@43.942,80.587
  Top Layer w0.711: J1_A1.3@33.499,73.282 33.943,73.726 34.566,73.726 38.313,77.473 43.318,77.473 43.937,78.091 43.937,80.581 J4_A1.10@43.942,80.587
  Bottom Layer w0.254: C146_A1.2@40.439,85.209 41.979,83.669 42.567,83.669 43.174,83.062 v1(43.892,83.062)
  Bottom Layer w0.305: v1(28.925,47.096) 28.902,47.073 28.808,47.073 28.387,47.493 27.808,47.493 26.669,48.632 26.669,67.275 32.351,72.956 33.173,72.956 J1_A1.3@33.499,73.282 ; D7_A1.1@38.313,83.574 38.468,83.574 39.611,82.43 43.26,82.43 v1(43.892,83.062)
  other v1: 28.925,42.038 28.925,42.881 28.925,43.724 28.925,44.567 28.925,45.41 28.925,46.253
CELL0_A2: C146_A2.2 D7_A2.1 J1_A2.3 J4_A2.10 R122_A2.1 R123_A2.1 R124_A2.1 R125_A2.1 R231_A2.1 | length 61.3
  Top Layer w0.229: R231_A2.1@138.445,71.082 138.445,73.279 J1_A2.3@138.499,73.332
  Top Layer w0.254: v1(148.892,83.112) 148.917,83.087 148.917,80.662 J4_A2.10@148.942,80.637
  Top Layer w0.711: J1_A2.3@138.499,73.332 138.943,73.776 139.566,73.776 143.313,77.523 148.318,77.523 148.937,78.141 148.937,80.631 J4_A2.10@148.942,80.637
  Bottom Layer w0.254: C146_A2.2@145.439,85.259 146.979,83.719 147.567,83.719 148.174,83.112 v1(148.892,83.112)
  Bottom Layer w0.305: v1(133.925,47.146) 133.902,47.123 133.808,47.123 133.387,47.543 132.808,47.543 131.669,48.682 131.669,67.325 134.466,70.122 135.454,70.122 J1_A2.3@138.499,73.167 J1_A2.3@138.499,73.332 ; D7_A2.1@143.313,83.624 143.468,83.624 144.611,82.48 148.26,82.48 v1(148.892,83.112)
  other v1: 133.925,42.088 133.925,42.931 133.925,43.774 133.925,44.617 133.925,45.46 133.925,46.303
CELL1_A1: C141_A1.2 J1_A1.4 J4_A1.31 R100_A1.1 R107_A1.1 R112_A1.1 R117_A1.1 R229_A1.1 | length 45
  Top Layer w0.229: R229_A1.1@36.003,71.032 36.021,71.05 36.021,73.264 J1_A1.4@36.039,73.282
  Top Layer w0.254: J4_A1.31@44.942,80.587 44.952,80.596 44.952,83.053 v1(44.961,83.062)
  Top Layer w0.711: J1_A1.4@36.039,73.282 39.319,76.562 43.696,76.562 44.942,77.808 J4_A1.31@44.942,80.587
  Bottom Layer w0.254: C141_A1.2@41.831,85.209 43.012,84.028 43.819,84.028 43.87,83.977 44.046,83.977 v1(44.961,83.062)
  Bottom Layer w0.305: v1(28.86,54.912) 27.854,55.918 27.854,65.202 34.689,72.037 34.689,72.755 35.039,73.105 35.861,73.105 J1_A1.4@36.039,73.282
  other v1: 28.86,49.854 28.86,50.697 28.86,51.54 28.86,52.383 28.86,53.226 28.86,54.069
CELL1_A2: C141_A2.2 J1_A2.4 J4_A2.31 R100_A2.1 R107_A2.1 R112_A2.1 R117_A2.1 R229_A2.1 | length 45
  Top Layer w0.229: R229_A2.1@141.003,71.082 141.021,71.1 141.021,73.314 J1_A2.4@141.039,73.332
  Top Layer w0.254: J4_A2.31@149.942,80.637 149.952,80.646 149.952,83.103 v1(149.961,83.112)
  Top Layer w0.711: J1_A2.4@141.039,73.332 144.319,76.612 148.696,76.612 149.942,77.858 J4_A2.31@149.942,80.637
  Bottom Layer w0.254: C141_A2.2@146.831,85.259 148.012,84.078 148.819,84.078 148.87,84.027 149.046,84.027 v1(149.961,83.112)
  Bottom Layer w0.305: v1(133.86,54.962) 132.854,55.968 132.854,65.252 139.689,72.087 139.689,72.805 140.039,73.155 140.861,73.155 J1_A2.4@141.039,73.332
  other v1: 133.86,49.904 133.86,50.747 133.86,51.59 133.86,52.433 133.86,53.276 133.86,54.119
CELL2_A1: C140_A1.2 J1_A1.5 J4_A1.11 R80_A1.1 R85_A1.1 R90_A1.1 R95_A1.1 R223_A1.1 | length 35.3
  Top Layer w0.229: R223_A1.1@38.56,71.032 38.57,71.041 38.57,73.273 J1_A1.5@38.579,73.282
  Top Layer w0.254: J4_A1.11@45.942,80.587 45.955,80.6 45.955,83.049 v1(45.968,83.062)
  Top Layer w0.711: J1_A1.5@38.579,73.282 40.947,75.651 44.073,75.651 45.942,77.52 J4_A1.11@45.942,80.587
  Bottom Layer w0.305: 28.471,64.329 v1(29.03,63.77) 28.994,63.806 28.994,64.52 37.579,73.105 38.401,73.105 J1_A1.5@38.579,73.282 ; C140_A1.2@43.223,85.209 43.924,84.507 44.018,84.507 44.069,84.456 44.574,84.456 v1(45.968,83.062)
  other v1: 29.03,58.713 29.03,59.556 29.03,60.398 29.03,61.241 29.03,62.084 29.03,62.927
CELL2_A2: C140_A2.2 J1_A2.5 J4_A2.11 R80_A2.1 R85_A2.1 R90_A2.1 R95_A2.1 R223_A2.1 | length 35.4
  Top Layer w0.229: R223_A2.1@143.56,71.082 143.57,71.091 143.57,73.323 J1_A2.5@143.579,73.332
  Top Layer w0.254: J4_A2.11@150.942,80.637 150.955,80.65 150.955,83.099 v1(150.968,83.112)
  Top Layer w0.711: J1_A2.5@143.579,73.332 145.947,75.701 149.073,75.701 150.942,77.57 J4_A2.11@150.942,80.637
  Bottom Layer w0.305: 133.471,64.379 v1(134.03,63.82) 133.994,63.856 133.994,64.57 138.169,68.745 139.156,68.745 J1_A2.5@143.579,73.167 J1_A2.5@143.579,73.332 ; C140_A2.2@148.223,85.259 148.924,84.557 149.018,84.557 149.069,84.506 149.574,84.506 v1(150.968,83.112)
  other v1: 134.03,58.763 134.03,59.606 134.03,60.448 134.03,61.291 134.03,62.134 134.03,62.977
CELL3_A1: C135_A1.2 J1_A1.6 J4_A1.32 R58_A1.1 R62_A1.1 R66_A1.1 R72_A1.1 R219_A1.1 | length 47.9
  Top Layer w0.229: R219_A1.1@41.118,71.032 J1_A1.6@41.118,73.282
  Top Layer w0.254: v1(46.868,83.062) 46.905,83.025 46.905,80.624 J4_A1.32@46.942,80.587
  Top Layer w0.711: J1_A1.6@41.119,73.282 42.576,74.739 44.451,74.739 46.942,77.231 J4_A1.32@46.942,80.587
  Bottom Layer w0.381: v1(37.671,47.252) 37.637,47.286 37.637,47.713 37.096,48.254 36.853,48.254 36.312,48.795 36.312,56.603 35.861,57.054 35.861,59.22 35.826,59.256 35.826,66.27 41.119,71.564 J1_A1.6@41.119,73.282 ; C135_A1.2@44.615,85.209 45.752,84.071 45.906,84.071 46.868,83.11 v1(46.868,83.062)
  other v1: 37.671,42.194 37.671,43.037 37.671,43.88 37.671,44.723 37.671,45.566 37.671,46.409
CELL3_A2: C135_A2.2 J1_A2.6 J4_A2.32 R58_A2.1 R62_A2.1 R66_A2.1 R72_A2.1 R219_A2.1 | length 47.9
  Top Layer w0.229: R219_A2.1@146.118,71.082 J1_A2.6@146.118,73.332
  Top Layer w0.254: v1(151.868,83.112) 151.905,83.075 151.905,80.674 J4_A2.32@151.942,80.637
  Top Layer w0.711: J1_A2.6@146.119,73.332 147.576,74.789 149.451,74.789 151.942,77.281 J4_A2.32@151.942,80.637
  Bottom Layer w0.381: v1(142.671,47.302) 142.637,47.336 142.637,47.763 142.096,48.304 141.853,48.304 141.312,48.845 141.312,56.653 140.861,57.104 140.861,59.27 140.826,59.306 140.826,66.32 146.119,71.614 J1_A2.6@146.119,73.332 ; C135_A2.2@149.615,85.259 150.752,84.121 150.906,84.121 151.868,83.16 v1(151.868,83.112)
  other v1: 142.671,42.244 142.671,43.087 142.671,43.93 142.671,44.773 142.671,45.616 142.671,46.459
CELL4_A1: C134_A1.2 J1_A1.7 J4_A1.12 R38_A1.1 R42_A1.1 R46_A1.1 R51_A1.1 R216_A1.1 | length 38.9
  Top Layer w0.229: J1_A1.7@43.659,73.282 43.667,73.274 43.667,71.04 R216_A1.1@43.676,71.032
  Top Layer w0.254: v1(47.868,83.062) 47.905,83.025 47.905,80.624 J4_A1.12@47.942,80.587
  Top Layer w0.711: J1_A1.7@43.659,73.282 43.899,73.282 44.446,73.828 44.828,73.828 47.942,76.943 J4_A1.12@47.942,80.587
  Bottom Layer w0.381: v1(37.671,55.068) 37.671,56.066 36.442,57.295 36.442,62.639 36.407,62.674 36.407,66.03 J1_A1.7@43.659,73.282 ; C134_A1.2@46.007,85.209 46.817,84.398 46.817,84.112 v1(47.868,83.062)
  other v1: 37.671,50.01 37.671,50.853 37.671,51.696 37.671,52.539 37.671,53.382 37.671,54.225
CELL4_A2: C134_A2.2 J1_A2.7 J4_A2.12 R38_A2.1 R42_A2.1 R46_A2.1 R51_A2.1 R216_A2.1 | length 38.9
  Top Layer w0.229: J1_A2.7@148.659,73.332 148.667,73.324 148.667,71.09 R216_A2.1@148.676,71.082
  Top Layer w0.254: v1(152.868,83.112) 152.905,83.075 152.905,80.674 J4_A2.12@152.942,80.637
  Top Layer w0.711: J1_A2.7@148.659,73.332 148.899,73.332 149.446,73.878 149.828,73.878 152.942,76.993 J4_A2.12@152.942,80.637
  Bottom Layer w0.381: v1(142.671,55.118) 142.671,56.116 141.442,57.345 141.442,62.689 141.407,62.724 141.407,66.08 J1_A2.7@148.659,73.332 ; C134_A2.2@151.007,85.259 151.817,84.448 151.817,84.162 v1(152.868,83.112)
  other v1: 142.671,50.06 142.671,50.903 142.671,51.746 142.671,52.589 142.671,53.432 142.671,54.275
CELL5_A1: C133_A1.2 J1_A1.8 J4_A1.33 R21_A1.1 R25_A1.1 R29_A1.1 R33_A1.1 R213_A1.1 | length 28.9
  Top Layer w0.229: J1_A1.8@46.199,73.282 46.216,73.265 46.216,71.049 R213_A1.1@46.233,71.032
  Top Layer w0.254: v1(48.874,83.062) 48.908,83.028 48.908,80.621 J4_A1.33@48.942,80.587
  Top Layer w0.711: J1_A1.8@46.199,73.282 46.199,73.523 46.593,73.916 46.593,74.106 48.942,76.456 J4_A1.33@48.942,80.587
  Bottom Layer w0.381: v1(37.671,63.926) 37.671,63.974 37.635,64.01 37.635,64.719 J1_A1.8@46.199,73.282 ; C133_A1.2@47.398,85.209 48.84,83.767 48.84,83.096 v1(48.874,83.062)
  other v1: 37.671,58.869 37.671,59.712 37.671,60.555 37.671,61.398 37.671,62.24 37.671,63.083
CELL5_A2: C133_A2.2 J1_A2.8 J4_A2.33 R21_A2.1 R25_A2.1 R29_A2.1 R33_A2.1 R213_A2.1 | length 28.9
  Top Layer w0.229: J1_A2.8@151.199,73.332 151.216,73.315 151.216,71.099 R213_A2.1@151.233,71.082
  Top Layer w0.254: v1(153.874,83.112) 153.908,83.078 153.908,80.671 J4_A2.33@153.942,80.637
  Top Layer w0.711: J1_A2.8@151.199,73.332 151.199,73.573 151.593,73.966 151.593,74.156 153.942,76.506 J4_A2.33@153.942,80.637
  Bottom Layer w0.381: v1(142.671,63.976) 142.671,64.024 142.635,64.06 142.635,64.769 J1_A2.8@151.199,73.332 ; C133_A2.2@152.398,85.259 153.84,83.817 153.84,83.146 v1(153.874,83.112)
  other v1: 142.671,58.919 142.671,59.762 142.671,60.605 142.671,61.448 142.671,62.29 142.671,63.133
CELL6_A1: C132_A1.2 J1_A1.9 J4_A1.13 R2_A1.1 R8_A1.1 R12_A1.1 R16_A1.1 R207_A1.1 | length 43.6
  Top Layer w0.229: J1_A1.9@48.739,73.282 48.765,73.256 48.765,71.058 R207_A1.1@48.791,71.032 ; J4_A1.13@49.942,80.587 49.969,80.613 49.969,83.065 v1(49.995,83.091)
  Top Layer w0.711: J1_A1.9@48.739,73.282 48.739,74.552 49.942,75.755 J4_A1.13@49.942,80.587
  Bottom Layer w0.305: v1(45.97,47.252) 45.968,47.254 45.968,47.682 44.476,49.174 44.476,69.019 J1_A1.9@48.739,73.282 ; C132_A1.2@48.79,85.209 49.038,84.961 49.038,84.351 49.518,83.872 49.518,83.637 49.995,83.16 v1(49.995,83.091)
  other v1: 45.97,42.194 45.97,43.037 45.97,43.88 45.97,44.723 45.97,45.566 45.97,46.409
CELL6_A2: C132_A2.2 J1_A2.9 J4_A2.13 R2_A2.1 R8_A2.1 R12_A2.1 R16_A2.1 R207_A2.1 | length 43.6
  Top Layer w0.229: J1_A2.9@153.739,73.332 153.765,73.306 153.765,71.108 R207_A2.1@153.791,71.082 ; J4_A2.13@154.942,80.637 154.969,80.663 154.969,83.115 v1(154.995,83.141)
  Top Layer w0.711: J1_A2.9@153.739,73.332 153.739,74.602 154.942,75.805 J4_A2.13@154.942,80.637
  Bottom Layer w0.305: v1(150.97,47.302) 150.968,47.304 150.968,47.732 149.476,49.224 149.476,69.069 J1_A2.9@153.739,73.332 ; C132_A2.2@153.79,85.259 154.038,85.011 154.038,84.401 154.518,83.922 154.518,83.687 154.995,83.21 v1(154.995,83.141)
  other v1: 150.97,42.244 150.97,43.087 150.97,43.93 150.97,44.773 150.97,45.616 150.97,46.459
CELL7_A1: C129_A1.2 J1_A1.10 J4_A1.34 R101_A1.1 R108_A1.1 R113_A1.1 R118_A1.1 R205_A1.1 | length 35.9
  Top Layer w0.229: J4_A1.34@50.942,80.587 50.969,80.613 50.969,83.065 v1(50.995,83.091) ; J1_A1.10@51.279,73.282 51.314,73.247 51.314,71.067 R205_A1.1@51.348,71.032
  Top Layer w0.711: J4_A1.34@50.942,80.587 50.942,74.143 51.109,73.977 51.109,73.452 J1_A1.10@51.279,73.282
  Bottom Layer w0.305: v1(45.97,55.068) 45.97,56.321 44.98,57.311 44.98,66.984 J1_A1.10@51.279,73.282 ; C129_A1.2@50.182,85.209 50.182,83.904 v1(50.995,83.091)
  other v1: 45.97,50.01 45.97,50.853 45.97,51.696 45.97,52.539 45.97,53.382 45.97,54.225
CELL7_A2: C129_A2.2 J1_A2.10 J4_A2.34 R101_A2.1 R108_A2.1 R113_A2.1 R118_A2.1 R205_A2.1 | length 35.9
  Top Layer w0.229: J4_A2.34@155.942,80.637 155.969,80.663 155.969,83.115 v1(155.995,83.141) ; J1_A2.10@156.279,73.332 156.314,73.297 156.314,71.117 R205_A2.1@156.348,71.082
  Top Layer w0.711: J4_A2.34@155.942,80.637 155.942,74.193 156.109,74.027 156.109,73.502 J1_A2.10@156.279,73.332
  Bottom Layer w0.305: v1(150.97,55.118) 150.97,56.371 149.98,57.361 149.98,67.034 J1_A2.10@156.279,73.332 ; C129_A2.2@155.182,85.259 155.182,83.954 v1(155.995,83.141)
  other v1: 150.97,50.06 150.97,50.903 150.97,51.746 150.97,52.589 150.97,53.432 150.97,54.275
CELL8_A1: C125_A1.2 J1_A1.11 J4_A1.14 R81_A1.1 R86_A1.1 R91_A1.1 R96_A1.1 R203_A1.1 | length 27.8
  Top Layer w0.229: J4_A1.14@51.942,80.587 51.968,80.613 51.968,83.088 v1(51.993,83.114) ; J1_A1.11@53.819,73.282 53.862,73.239 53.862,71.075 R203_A1.1@53.906,71.032
  Top Layer w0.711: J4_A1.14@51.942,80.587 51.942,75.159 J1_A1.11@53.819,73.282
  Bottom Layer w0.305: v1(45.97,63.926) 45.97,64.554 53.674,72.258 53.674,73.138 J1_A1.11@53.819,73.282 ; C125_A1.2@51.574,85.209 51.574,83.602 51.993,83.183 v1(51.993,83.114)
  other v1: 45.97,58.869 45.97,59.712 45.97,60.555 45.97,61.398 45.97,62.24 45.97,63.083
CELL8_A2: C125_A2.2 J1_A2.11 J4_A2.14 R81_A2.1 R86_A2.1 R91_A2.1 R96_A2.1 R203_A2.1 | length 27.8
  Top Layer w0.229: J4_A2.14@156.942,80.637 156.968,80.663 156.968,83.138 v1(156.993,83.164) ; J1_A2.11@158.819,73.332 158.862,73.289 158.862,71.125 R203_A2.1@158.906,71.082
  Top Layer w0.711: J4_A2.14@156.942,80.637 156.942,75.209 J1_A2.11@158.819,73.332
  Bottom Layer w0.305: v1(150.97,63.976) 150.97,64.604 158.674,72.308 158.674,73.188 J1_A2.11@158.819,73.332 ; C125_A2.2@156.574,85.259 156.574,83.652 156.993,83.233 v1(156.993,83.164)
  other v1: 150.97,58.919 150.97,59.762 150.97,60.605 150.97,61.448 150.97,62.29 150.97,63.133
CELL9_A1: C123_A1.2 J1_A1.12 J2_A1.1 J4_A1.35 R59_A1.1 R63_A1.1 R67_A1.1 R73_A1.1 R201_A1.1 | length 50.8
  Top Layer w0.229: J1_A1.12@56.359,73.282 56.399,73.242 56.399,71.107 R201_A1.1@56.438,71.067
  Top Layer w0.254: J4_A1.35@52.942,79.898 52.992,79.948 52.992,83.014 v1(53.042,83.064)
  Top Layer w0.711: J4_A1.35@52.942,79.898 52.942,76.618 56.278,73.282 J1_A1.12@56.359,73.282 J2_A1.1@63.373,73.282
  Bottom Layer w0.305: C123_A1.2@52.966,85.209 53.004,85.17 53.004,83.103 v1(53.042,83.064) ; v1(54.326,47.252) 52.848,48.73 52.848,69.442 56.359,72.953 J1_A1.12@56.359,73.282
  other v1: 54.326,42.194 54.326,43.037 54.326,43.88 54.326,44.723 54.326,45.566 54.326,46.409
CELL9_A2: C123_A2.2 J1_A2.12 J2_A2.1 J4_A2.35 R59_A2.1 R63_A2.1 R67_A2.1 R73_A2.1 R201_A2.1 | length 51
  Top Layer w0.229: J1_A2.12@161.399,73.292 161.399,71.157 R201_A2.1@161.438,71.117
  Top Layer w0.254: J4_A2.35@157.942,79.948 157.992,79.998 157.992,83.064 v1(158.042,83.114)
  Top Layer w0.711: J4_A2.35@157.942,79.948 157.942,76.668 161.359,73.251 J1_A2.12@161.359,73.167 164.767,73.167 164.932,73.332 J2_A2.1@168.373,73.332
  Bottom Layer w0.305: C123_A2.2@157.966,85.259 158.004,85.22 158.004,83.153 v1(158.042,83.114) ; v1(159.326,47.302) 157.848,48.78 157.848,69.492 161.359,73.003 J1_A2.12@161.359,73.332
  other v1: 159.326,42.244 159.326,43.087 159.326,43.93 159.326,44.773 159.326,45.616 159.326,46.459
CELL10_A1: C119_A1.2 J2_A1.2 J4_A1.15 R39_A1.1 R43_A1.1 R47_A1.1 R52_A1.1 R199_A1.1 | length 50
  Top Layer w0.229: J2_A1.2@65.913,73.282 65.925,73.271 65.925,71.078 R199_A1.1@65.936,71.067
  Top Layer w0.305: J4_A1.15@53.948,80.581 53.951,80.585 53.951,83.037 v1(53.96,83.046)
  Top Layer w0.711: J4_A1.15@53.948,80.581 53.948,76.901 56.109,74.739 64.456,74.739 J2_A1.2@65.913,73.282
  Bottom Layer w0.305: v1(53.96,83.046) 53.96,83.115 54.358,83.513 C119_A1.2@54.358,85.209 ; v1(54.326,55.068) 53.505,55.889 53.505,64.489 57.778,68.762 61.393,68.762 J2_A1.2@65.913,73.282
  other v1: 54.326,50.01 54.326,50.853 54.326,51.696 54.326,52.539 54.326,53.382 54.326,54.225
CELL10_A2: C119_A2.2 J2_A2.2 J4_A2.15 R39_A2.1 R43_A2.1 R47_A2.1 R52_A2.1 R199_A2.1 | length 50
  Top Layer w0.229: J2_A2.2@170.913,73.332 170.925,73.321 170.925,71.128 R199_A2.1@170.936,71.117
  Top Layer w0.305: J4_A2.15@158.948,80.631 158.951,80.635 158.951,83.087 v1(158.96,83.096)
  Top Layer w0.711: J4_A2.15@158.948,80.631 158.948,76.951 161.109,74.789 169.456,74.789 J2_A2.2@170.913,73.332
  Bottom Layer w0.305: v1(158.96,83.096) 158.96,83.165 159.358,83.563 C119_A2.2@159.358,85.259 ; v1(159.326,55.118) 158.505,55.939 158.505,64.539 162.778,68.812 166.393,68.812 J2_A2.2@170.913,73.332
  other v1: 159.326,50.06 159.326,50.903 159.326,51.746 159.326,52.589 159.326,53.432 159.326,54.275
CELL11_A1: C115_A1.2 J2_A1.3 J4_A1.36 R22_A1.1 R26_A1.1 R30_A1.1 R34_A1.1 R197_A1.1 | length 43.4
  Top Layer w0.229: J2_A1.3@68.453,73.282 68.463,73.272 68.463,71.077 R197_A1.1@68.474,71.067
  Top Layer w0.305: J4_A1.36@54.948,80.581 54.951,80.585 54.951,83.037 v1(54.96,83.046)
  Top Layer w0.711: J4_A1.36@54.948,80.581 54.948,77.723 57.021,75.651 66.085,75.651 J2_A1.3@68.453,73.282
  Bottom Layer w0.305: v1(54.326,63.926) 56.64,66.24 61.411,66.24 J2_A1.3@68.453,73.282 ; v1(54.96,83.046) 55.75,83.836 C115_A1.2@55.75,85.209
  other v1: 54.326,58.869 54.326,59.712 54.326,60.555 54.326,61.398 54.326,62.24 54.326,63.083
CELL11_A2: C115_A2.2 J2_A2.3 J4_A2.36 R22_A2.1 R26_A2.1 R30_A2.1 R34_A2.1 R197_A2.1 | length 43.4
  Top Layer w0.229: J2_A2.3@173.453,73.332 173.463,73.322 173.463,71.127 R197_A2.1@173.474,71.117
  Top Layer w0.305: J4_A2.36@159.948,80.631 159.951,80.635 159.951,83.087 v1(159.96,83.096)
  Top Layer w0.711: J4_A2.36@159.948,80.631 159.948,77.773 162.021,75.701 171.085,75.701 J2_A2.3@173.453,73.332
  Bottom Layer w0.305: v1(159.326,63.976) 161.64,66.29 166.411,66.29 J2_A2.3@173.453,73.332 ; v1(159.96,83.096) 160.75,83.886 C115_A2.2@160.75,85.259
  other v1: 159.326,58.919 159.326,59.762 159.326,60.605 159.326,61.448 159.326,62.29 159.326,63.133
